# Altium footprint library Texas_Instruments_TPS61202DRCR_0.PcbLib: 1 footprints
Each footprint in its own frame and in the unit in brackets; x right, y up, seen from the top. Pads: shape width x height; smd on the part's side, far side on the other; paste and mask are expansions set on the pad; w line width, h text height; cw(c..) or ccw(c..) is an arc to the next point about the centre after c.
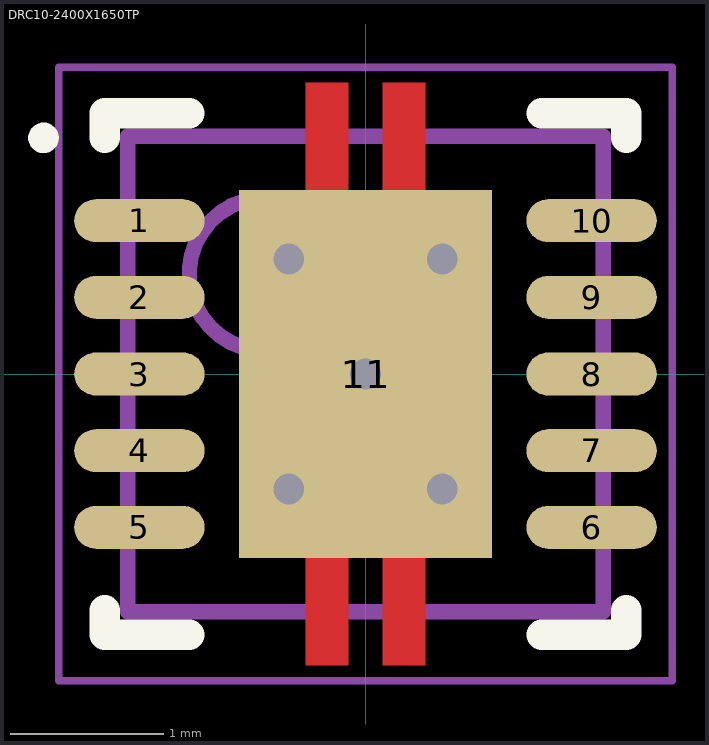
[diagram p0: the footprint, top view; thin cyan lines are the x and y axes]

## DRC10-2400X1650TP [mm] "SON, 10-Leads, Body 3x3mm, Pitch 0.5mm, Thermal Pad 2.4x1.65mm, TI Recommended"
height 1
pads (11):
  oval 0.85x0.28 smd paste-0.025 mask+0.07: 1(-1.475,1) 2(-1.475,0.5) 3(-1.475,0) 4(-1.475,-0.5) 5(-1.475,-1) 6(1.475,-1) 7(1.475,-0.5) 8(1.475,0) 9(1.475,0.5) 10(1.475,1)
  rect 1.65x2.4 smd paste-0.825 mask+0.07: 11(0,0)
via 0,0 diameter 0.5 hole 0.2
via 0.5,0.75 diameter 0.5 hole 0.2
via -0.5,0.75 diameter 0.5 hole 0.2
via -0.5,-0.75 diameter 0.5 hole 0.2
via 0.5,-0.75 diameter 0.5 hole 0.2
Top Layer:
  rectangle: -0.39,1.2 -0.11,1.9
  region: 0.39,1.9 0.11,1.9 0.11,1.2 0.39,1.2
  region: 0.39,-1.2 0.11,-1.2 0.11,-1.9 0.39,-1.9
  rectangle: -0.39,-1.9 -0.11,-1.2
Top Overlay:
  circle w0.1: c-2.1,1.54 r0.05
  lines w0.2: -1.7,-1.54 -1.7,-1.7 -1.15,-1.7 ; -1.7,1.54 -1.7,1.7 -1.15,1.7 ; 1.15,-1.7 1.7,-1.7 1.7,-1.54 ; 1.15,1.7 1.7,1.7 1.7,1.54
Top Paste:
  rectangle: -0.79,0.11 -0.11,1.16
  rectangle: -0.38,1.38 -0.12,1.88
  region: 0.38,1.88 0.12,1.88 0.12,1.38 0.38,1.38
  region: 0.38,-1.38 0.12,-1.38 0.12,-1.88 0.38,-1.88
  rectangle: -0.38,-1.88 -0.12,-1.38
  region: 0.79,1.16 0.11,1.16 0.11,0.11 0.79,0.11
  region: 0.79,-0.11 0.11,-0.11 0.11,-1.16 0.79,-1.16
  rectangle: -0.79,-1.16 -0.11,-0.11
Mechanical 13:
  circle w0.1: c-0.65,0.65 r0.5
  lines w0.1: -1.55,-1.55 -1.55,1.55 1.55,1.55 1.55,-1.55 -1.55,-1.55
Mechanical 15:
  lines w0.05: -2,-2 -2,2 2,2 2,-2 -2,-2
3D body: height 1, standoff 0, extent -1.55,-1.55 1.55,1.55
